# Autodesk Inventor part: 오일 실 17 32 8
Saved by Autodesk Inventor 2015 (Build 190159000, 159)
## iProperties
Created: 2026-05
Part Number: 오일 실 17 32 8
Material: 일반
Document SubType Name: Modeling
Designer: 104
Density: 1 g/cm^3
Appearance: 기본값
Author: 104
Author: jhkim
Description: 오일-실
Creation Date: 2026-04-27
Sending System: Autodesk Inventor 2027
Preprocessor: ST-DEVELOPER v20.1
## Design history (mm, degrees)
node "오일 실 17 32 81"
body "Solid1"
node "기준1"
